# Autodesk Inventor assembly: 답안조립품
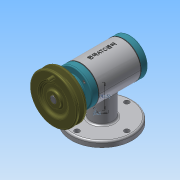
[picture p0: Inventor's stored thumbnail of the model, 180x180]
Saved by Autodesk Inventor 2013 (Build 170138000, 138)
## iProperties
Created: 2018-11
Part Number: 답안조립품
Document SubType Name: Assembly
Designer: Administrator
Author: Administrator
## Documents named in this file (18)
- C:\Users\Administrator\Desktop\381107V1002\답안조립품.iam
- C:\Users\Administrator\Desktop\381107V1002\본체.ipt
- C:\Users\Administrator\Desktop\381107V1002\V-벨트풀리.ipt
- C:\Users\Administrator\Desktop\381107V1002\가변스프링.ipt
- C:\Users\Administrator\Desktop\381107V1002\개스킷.ipt
- C:\Users\Administrator\Desktop\381107V1002\뒤커버.ipt
- C:\Users\Administrator\Desktop\381107V1002\멈춤나사 M3x8.ipt
- C:\Users\Administrator\Desktop\381107V1002\베어링 6201.ipt
- C:\Users\Administrator\Desktop\381107V1002\베어링 6202.ipt
- C:\Users\Administrator\Desktop\381107V1002\본체커버.ipt
- C:\Users\Administrator\Desktop\381107V1002\볼트 M3x0.5x8.ipt
- C:\Users\Administrator\Desktop\381107V1002\슬라이드.ipt
- C:\Users\Administrator\Desktop\381107V1002\앞커버.ipt
- C:\Users\Administrator\Desktop\381107V1002\오일 실 12 22 7.ipt
- 오일 실 12 22 7.ipt
- C:\Users\Administrator\Desktop\381107V1002\키 4x4x18.ipt
- 키 4x4x18.ipt
- C:\Users\Administrator\Desktop\381107V1002\편심축.ipt
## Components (4 placed, 3 different names)
1. V-벨트풀리:1
2. 가변스프링:1
3. 개스킷:1
4. 개스킷:2
